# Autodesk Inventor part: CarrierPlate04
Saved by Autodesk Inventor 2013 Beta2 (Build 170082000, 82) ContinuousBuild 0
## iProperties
Created: 2008-02
Part Number: CarrierPlate04
Document SubType Name: Modeling
Designer: grh
Density: 1 g/cm^3
Material: Generic
Author: grh
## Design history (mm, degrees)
sketch "Sketch1"
  geometry: L1 (48.514, 0)-(0, 0); L2 (0, 0)-(37.164, 31.184); L3 (8.424, 47.777)-(0, 0); L4 (-24.257, 42.014)-(0, 0); C1 r 53.34 at (0, 0)
  constraints: 8 end point, 3 equal length, 1 centre point, 1 horizontal, 1 other
  dimensions: "BlankDiameter" = 106.68 diameter of C1; "PlanetRadius" = 48.514 distance of L1.start L1.end; "Angle1" = 40 deg angle of L2 L1; "Angle2" = 40 deg angle of L3 L2; "Angle3" = 40 deg angle of L4 L3
extrude "Extrusion1" new body sketch "Sketch1" stored distance "d9" = 13.97; taper "d10" = 0 deg
node "Axis1"
node "Axis2"
node "Axis3"
node "Axis4"
node "Axis5"
body "Solid1"
